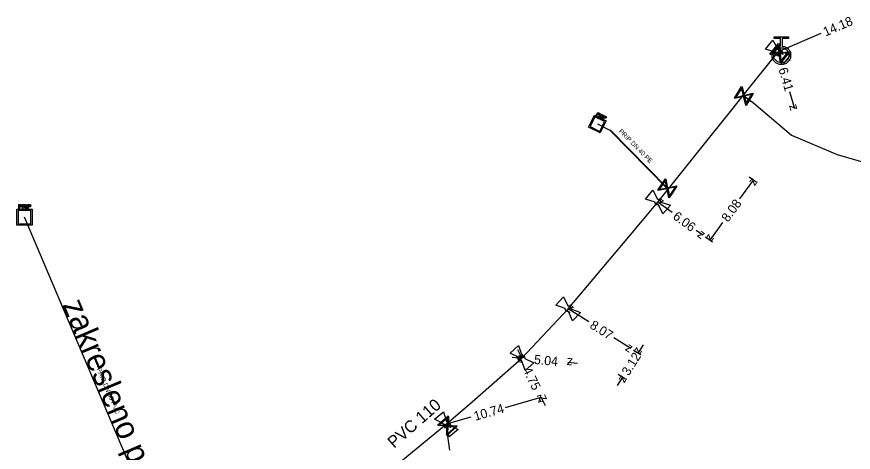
# Model space of a CAD drawing. Extents: x -638315 to -636370, y -1116147 to -1115110.
# Drawn here: x -637259.8 to -637168.7, y -1115907.4 to -1115860.1 of the extents above; entities that cross this region are included whole.
import ezdxf

# ---------------------------------------------------------------- set-up
doc = ezdxf.new("R2010")
doc.units = 0
for name, color, linetype in [('Default', 7, 'Continuous'), ('VP Chránička', 7, 'Continuous'), ('VP Chránička - okraje', 7, 'Continuous'), ('VP Hydrant', 7, 'Continuous'), ('VP Kótování', 7, 'Continuous'), ('VP Lomový bod', 7, 'Continuous'), ('VP Popis nerozlišený', 7, 'Continuous'), ('VP Popis přípojky', 7, 'Continuous'), ('VP Přípojka', 7, 'Continuous'), ('VP Řad', 7, 'Continuous'), ('VP Řad - popis', 7, 'Continuous'), ('VP Šachta', 7, 'Continuous'), ('VP Šoupě', 7, 'Continuous')]:
    doc.layers.add(name, color=color, linetype=linetype)

msp = doc.modelspace()

# ---------------------------------------------------------------- linework, layer by layer
at = {"layer": 'Default'}
for points in [[(-637176.478, -1115863.274), (-637176.119, -1115863.303), (-637175.861, -1115863.563), (-637175.57, -1115863.856), (-637175.57, -1115864.272), (-637175.57, -1115864.686), (-637175.863, -1115864.978), (-637176.156, -1115865.27), (-637176.572, -1115865.27), (-637176.984, -1115865.27), (-637177.277, -1115864.978), (-637177.57, -1115864.686), (-637177.57, -1115864.272), (-637177.57, -1115863.856), (-637177.279, -1115863.563), (-637177.021, -1115863.301), (-637176.662, -1115863.274)], [(-637176.572, -1115863.456), (-637176.91, -1115863.456), (-637177.147, -1115863.693), (-637177.384, -1115863.93), (-637177.384, -1115864.268), (-637177.384, -1115864.606), (-637177.147, -1115864.843), (-637176.91, -1115865.081), (-637176.572, -1115865.081), (-637176.236, -1115865.081), (-637175.998, -1115864.843), (-637175.759, -1115864.606), (-637175.759, -1115864.268), (-637175.759, -1115863.93), (-637175.997, -1115863.693), (-637176.234, -1115863.456), (-637176.572, -1115863.456)], [(-637176.92, -1115863.535), (-637176.826, -1115863.535), (-637176.736, -1115863.583), (-637176.646, -1115863.632), (-637176.596, -1115863.722), (-637176.545, -1115863.812), (-637176.545, -1115863.91), (-637176.545, -1115864.008), (-637176.594, -1115864.097), (-637176.644, -1115864.186), (-637176.733, -1115864.236), (-637176.823, -1115864.285), (-637176.92, -1115864.285), (-637177.017, -1115864.285), (-637177.107, -1115864.236), (-637177.196, -1115864.186), (-637177.246, -1115864.097), (-637177.295, -1115864.008), (-637177.295, -1115863.91), (-637177.295, -1115863.812), (-637177.245, -1115863.722), (-637177.194, -1115863.632), (-637177.105, -1115863.583), (-637177.015, -1115863.535), (-637176.92, -1115863.535)], [(-637176.92, -1115863.582), (-637177.003, -1115863.582), (-637177.082, -1115863.624), (-637177.16, -1115863.666), (-637177.204, -1115863.745), (-637177.248, -1115863.824), (-637177.248, -1115863.91), (-637177.248, -1115863.996), (-637177.205, -1115864.074), (-637177.162, -1115864.151), (-637177.084, -1115864.195), (-637177.005, -1115864.238), (-637176.92, -1115864.238), (-637176.835, -1115864.238), (-637176.756, -1115864.195), (-637176.678, -1115864.151), (-637176.635, -1115864.074), (-637176.592, -1115863.996), (-637176.592, -1115863.91), (-637176.592, -1115863.824), (-637176.636, -1115863.745), (-637176.681, -1115863.666), (-637176.759, -1115863.624), (-637176.838, -1115863.582), (-637176.92, -1115863.582)], [(-637176.863, -1115864.217), (-637176.915, -1115864.227), (-637176.969, -1115864.218), (-637177.052, -1115864.205), (-637177.115, -1115864.154), (-637177.179, -1115864.102), (-637177.211, -1115864.022), (-637177.232, -1115863.973), (-637177.233, -1115863.92)], [(-637176.977, -1115863.601), (-637176.926, -1115863.592), (-637176.873, -1115863.6), (-637176.788, -1115863.615), (-637176.724, -1115863.666), (-637176.661, -1115863.717), (-637176.629, -1115863.795), (-637176.609, -1115863.846), (-637176.608, -1115863.899)], [(-637196.454, -1115870.551), (-637196.422, -1115870.567), (-637196.406, -1115870.579), (-637196.386, -1115870.594), (-637196.374, -1115870.613), (-637196.363, -1115870.632), (-637196.363, -1115870.656), (-637196.364, -1115870.681), (-637196.375, -1115870.705), (-637196.396, -1115870.747), (-637196.435, -1115870.762), (-637196.474, -1115870.778), (-637196.543, -1115870.744)], [(-637196.524, -1115870.707), (-637196.483, -1115870.727), (-637196.458, -1115870.72), (-637196.434, -1115870.713), (-637196.42, -1115870.685), (-637196.41, -1115870.665), (-637196.413, -1115870.646), (-637196.416, -1115870.627), (-637196.431, -1115870.614), (-637196.44, -1115870.606), (-637196.47, -1115870.591)], [(-637196.224, -1115870.979), (-637196.228, -1115870.941), (-637196.233, -1115870.919), (-637196.237, -1115870.898), (-637196.244, -1115870.887), (-637196.251, -1115870.876), (-637196.26, -1115870.869), (-637196.265, -1115870.864), (-637196.282, -1115870.856)], [(-637196.223, -1115870.84), (-637196.193, -1115870.854), (-637196.174, -1115870.856), (-637196.154, -1115870.858), (-637196.14, -1115870.849), (-637196.125, -1115870.84), (-637196.117, -1115870.823), (-637196.106, -1115870.801), (-637196.116, -1115870.779), (-637196.125, -1115870.756), (-637196.161, -1115870.738)], [(-637196.145, -1115870.701), (-637196.102, -1115870.722), (-637196.083, -1115870.742), (-637196.065, -1115870.762), (-637196.063, -1115870.79), (-637196.06, -1115870.818), (-637196.073, -1115870.845), (-637196.09, -1115870.88), (-637196.123, -1115870.892), (-637196.156, -1115870.905), (-637196.206, -1115870.889), (-637196.193, -1115870.906), (-637196.188, -1115870.918), (-637196.178, -1115870.943), (-637196.174, -1115870.978)], [(-637195.733, -1115870.902), (-637195.701, -1115870.918), (-637195.685, -1115870.93), (-637195.664, -1115870.945), (-637195.653, -1115870.964), (-637195.642, -1115870.983), (-637195.642, -1115871.007), (-637195.643, -1115871.032), (-637195.654, -1115871.056), (-637195.675, -1115871.098), (-637195.714, -1115871.113), (-637195.753, -1115871.129), (-637195.822, -1115871.096)], [(-637195.803, -1115871.058), (-637195.762, -1115871.079), (-637195.737, -1115871.071), (-637195.713, -1115871.064), (-637195.699, -1115871.036), (-637195.689, -1115871.016), (-637195.692, -1115870.997), (-637195.695, -1115870.978), (-637195.71, -1115870.965), (-637195.719, -1115870.957), (-637195.749, -1115870.942)], [(-637189.97, -1115880.548), (-637190.022, -1115880.557), (-637190.076, -1115880.547), (-637190.159, -1115880.531), (-637190.221, -1115880.479), (-637190.284, -1115880.426), (-637190.314, -1115880.344), (-637190.333, -1115880.295), (-637190.333, -1115880.242)], [(-637190.07, -1115879.929), (-637190.018, -1115879.922), (-637189.966, -1115879.931), (-637189.881, -1115879.948), (-637189.819, -1115880.001), (-637189.756, -1115880.053), (-637189.727, -1115880.132), (-637189.708, -1115880.184), (-637189.707, -1115880.236)], [(-637259.447, -1115880.507), (-637259.404, -1115880.507), (-637259.381, -1115880.511), (-637259.35, -1115880.517), (-637259.328, -1115880.532), (-637259.306, -1115880.547), (-637259.293, -1115880.573), (-637259.281, -1115880.599), (-637259.281, -1115880.631), (-637259.281, -1115880.687), (-637259.315, -1115880.725), (-637259.35, -1115880.762), (-637259.441, -1115880.762)], [(-637259.441, -1115880.712), (-637259.385, -1115880.712), (-637259.362, -1115880.692), (-637259.34, -1115880.671), (-637259.34, -1115880.633), (-637259.34, -1115880.607), (-637259.353, -1115880.588), (-637259.366, -1115880.569), (-637259.388, -1115880.563), (-637259.403, -1115880.558), (-637259.442, -1115880.558)], [(-637258.973, -1115880.848), (-637258.998, -1115880.809), (-637259.014, -1115880.788), (-637259.031, -1115880.768), (-637259.044, -1115880.76), (-637259.057, -1115880.752), (-637259.07, -1115880.749), (-637259.079, -1115880.746), (-637259.101, -1115880.746)], [(-637259.045, -1115880.697), (-637259.006, -1115880.697), (-637258.984, -1115880.689), (-637258.962, -1115880.681), (-637258.951, -1115880.664), (-637258.94, -1115880.646), (-637258.94, -1115880.624), (-637258.94, -1115880.595), (-637258.962, -1115880.575), (-637258.984, -1115880.555), (-637259.032, -1115880.555)], [(-637259.033, -1115880.507), (-637258.976, -1115880.507), (-637258.946, -1115880.519), (-637258.916, -1115880.53), (-637258.899, -1115880.56), (-637258.881, -1115880.589), (-637258.881, -1115880.624), (-637258.881, -1115880.671), (-637258.91, -1115880.702), (-637258.94, -1115880.733), (-637259.001, -1115880.741), (-637258.979, -1115880.753), (-637258.968, -1115880.763), (-637258.943, -1115880.785), (-637258.921, -1115880.82)], [(-637258.484, -1115880.508), (-637258.442, -1115880.508), (-637258.418, -1115880.513), (-637258.387, -1115880.519), (-637258.366, -1115880.533), (-637258.344, -1115880.548), (-637258.331, -1115880.574), (-637258.319, -1115880.601), (-637258.319, -1115880.633), (-637258.319, -1115880.689), (-637258.353, -1115880.726), (-637258.387, -1115880.763), (-637258.478, -1115880.763)], [(-637258.478, -1115880.714), (-637258.423, -1115880.714), (-637258.4, -1115880.693), (-637258.377, -1115880.673), (-637258.377, -1115880.634), (-637258.377, -1115880.608), (-637258.39, -1115880.589), (-637258.404, -1115880.57), (-637258.426, -1115880.564), (-637258.44, -1115880.56), (-637258.48, -1115880.56)], [(-637199.767, -1115892.151), (-637199.819, -1115892.157), (-637199.873, -1115892.144), (-637199.954, -1115892.124), (-637200.014, -1115892.068), (-637200.074, -1115892.012), (-637200.1, -1115891.929), (-637200.116, -1115891.879), (-637200.113, -1115891.826)], [(-637199.833, -1115891.528), (-637199.782, -1115891.523), (-637199.73, -1115891.535), (-637199.646, -1115891.556), (-637199.586, -1115891.612), (-637199.527, -1115891.668), (-637199.502, -1115891.749), (-637199.485, -1115891.801), (-637199.488, -1115891.854)], [(-637204.827, -1115897.513), (-637204.88, -1115897.513), (-637204.932, -1115897.495), (-637205.011, -1115897.468), (-637205.065, -1115897.406), (-637205.119, -1115897.344), (-637205.137, -1115897.259), (-637205.148, -1115897.208), (-637205.14, -1115897.155)], [(-637204.833, -1115896.886), (-637204.781, -1115896.886), (-637204.73, -1115896.903), (-637204.649, -1115896.933), (-637204.595, -1115896.994), (-637204.541, -1115897.056), (-637204.524, -1115897.138), (-637204.513, -1115897.192), (-637204.521, -1115897.244)], [(-637213.069, -1115904.721), (-637213.122, -1115904.72), (-637213.173, -1115904.701), (-637213.252, -1115904.67), (-637213.303, -1115904.607), (-637213.355, -1115904.544), (-637213.37, -1115904.458), (-637213.38, -1115904.406), (-637213.37, -1115904.354)], [(-637213.053, -1115904.095), (-637213.002, -1115904.097), (-637212.951, -1115904.116), (-637212.871, -1115904.148), (-637212.82, -1115904.211), (-637212.768, -1115904.275), (-637212.754, -1115904.358), (-637212.744, -1115904.411), (-637212.754, -1115904.463)]]:
    msp.add_open_spline(points, degree=3, dxfattribs=at)
at = {"layer": 'VP Chránička'}
msp.add_lwpolyline([(-637188.995, -1115878.735), (-637195.242, -1115872.412)], dxfattribs=at)
at = {"layer": 'VP Chránička - okraje'}
for points in [[(-637189.017, -1115878.757), (-637195.264, -1115872.434)], [(-637195.219, -1115872.39), (-637188.973, -1115878.713)]]:
    msp.add_lwpolyline(points, dxfattribs=at)
at = {"layer": 'VP Hydrant'}
msp.add_lwpolyline([(-637176.662, -1115863.274), (-637176.662, -1115862.454), (-637177.351, -1115862.454), (-637177.351, -1115862.27), (-637175.789, -1115862.27), (-637175.789, -1115862.454), (-637176.478, -1115862.454), (-637176.478, -1115863.274)], dxfattribs=at)
at = {"layer": 'VP Kótování'}
for points in [[(-637172.285, -1115861.921), (-637176.92, -1115863.91)], [(-637176.519, -1115865.291), (-637176.92, -1115863.91)], [(-637175.672, -1115868.204), (-637175.13, -1115870.07)], [(-637180.077, -1115877.496), (-637179.324, -1115878.047)], [(-637181.1, -1115879.886), (-637179.606, -1115877.84)], [(-637188.465, -1115881.375), (-637190.02, -1115880.24)], [(-637182.992, -1115882.477), (-637184.37, -1115884.365)], [(-637185.848, -1115883.287), (-637185.124, -1115883.815)], [(-637184.841, -1115884.021), (-637184.088, -1115884.572)], [(-637197.548, -1115893.26), (-637199.8, -1115891.84)], [(-637194.835, -1115894.971), (-637192.977, -1115896.143)], [(-637191.618, -1115895.758), (-637192.179, -1115896.647)], [(-637205.292, -1115896.257), (-637204.83, -1115897.2)], [(-637192.681, -1115896.33), (-637191.882, -1115896.833)], [(-637205.875, -1115897.098), (-637204.83, -1115897.2)], [(-637198.765, -1115897.792), (-637199.81, -1115897.69)], [(-637194.402, -1115900.172), (-637193.842, -1115899.284)], [(-637194.344, -1115898.967), (-637193.545, -1115899.47)], [(-637206.621, -1115902.569), (-637202.74, -1115901.46)], [(-637202.278, -1115902.403), (-637202.74, -1115901.46)], [(-637210.379, -1115903.643), (-637213.062, -1115904.409)], [(-637212.681, -1115907.23), (-637213.062, -1115904.409)]]:
    msp.add_lwpolyline(points, dxfattribs=at)
at = {"layer": 'VP Lomový bod'}
for points in [[(-637178.286, -1115863.615), (-637177.504, -1115862.64), (-637176.977, -1115863.601)], [(-637177.233, -1115863.92), (-637178.286, -1115863.615)], [(-637176.608, -1115863.899), (-637175.554, -1115864.204), (-637176.336, -1115865.179), (-637176.863, -1115864.217)], [(-637191.378, -1115879.912), (-637190.573, -1115878.956), (-637190.07, -1115879.929)], [(-637190.333, -1115880.242), (-637191.378, -1115879.912)], [(-637189.707, -1115880.236), (-637188.661, -1115880.567), (-637189.467, -1115881.523), (-637189.97, -1115880.548)], [(-637201.139, -1115891.44), (-637200.284, -1115890.529), (-637199.833, -1115891.528)], [(-637200.113, -1115891.826), (-637201.139, -1115891.44)], [(-637199.488, -1115891.854), (-637198.461, -1115892.24), (-637199.316, -1115893.151), (-637199.767, -1115892.151)], [(-637206.124, -1115896.671), (-637205.183, -1115895.848), (-637204.833, -1115896.886)], [(-637205.14, -1115897.155), (-637206.124, -1115896.671)], [(-637204.521, -1115897.244), (-637203.536, -1115897.729), (-637204.477, -1115898.552), (-637204.827, -1115897.513)], [(-637214.337, -1115903.837), (-637213.369, -1115903.046), (-637213.053, -1115904.095)], [(-637213.37, -1115904.354), (-637214.337, -1115903.837)], [(-637212.754, -1115904.463), (-637211.786, -1115904.981), (-637212.754, -1115905.772), (-637213.069, -1115904.721)]]:
    msp.add_lwpolyline(points, dxfattribs=at)
at = {"layer": 'VP Přípojka'}
for points in [[(-637176.637, -1115864.19), (-637176.766, -1115864.037), (-637176.92, -1115863.91)], [(-637180.72, -1115868.647), (-637180.66, -1115868.69), (-637179.56, -1115869.48), (-637175.49, -1115872.98), (-637170.49, -1115875.08), (-637164.61, -1115876.76), (-637159.9, -1115877.14), (-637154.27, -1115876.95)], [(-637196.612, -1115871.747), (-637195.242, -1115872.412), (-637188.995, -1115878.735), (-637188.874, -1115878.812)], [(-637244.12, -1115916.89), (-637258.991, -1115881.881)], [(-637213.062, -1115904.409), (-637212.92, -1115904.55)]]:
    msp.add_lwpolyline(points, dxfattribs=at)
at = {"layer": 'VP Řad'}
msp.add_lwpolyline([(-637237.94, -1115924.63), (-637234.89, -1115921.16), (-637222.26, -1115911.93), (-637213.062, -1115904.409), (-637210.258, -1115901.954), (-637204.83, -1115897.2), (-637199.8, -1115891.84), (-637193.2, -1115884.012), (-637190.02, -1115880.24), (-637188.874, -1115878.812), (-637184.355, -1115873.178), (-637181.977, -1115870.214), (-637180.72, -1115868.647), (-637176.92, -1115863.91)], dxfattribs=at)
at = {"layer": 'VP Šachta'}
for points in [[(-637195.661, -1115871.405), (-637196.295, -1115872.711), (-637197.566, -1115872.094), (-637196.933, -1115870.788), (-637195.661, -1115871.405)], [(-637196.878, -1115870.952), (-637197.404, -1115872.036), (-637196.35, -1115872.548), (-637195.824, -1115871.464), (-637196.878, -1115870.952)], [(-637196.732, -1115870.816), (-637196.575, -1115870.493), (-637196.454, -1115870.551)], [(-637196.543, -1115870.744), (-637196.626, -1115870.704), (-637196.69, -1115870.836), (-637196.732, -1115870.816)], [(-637196.47, -1115870.591), (-637196.552, -1115870.551), (-637196.608, -1115870.667)], [(-637196.608, -1115870.667), (-637196.524, -1115870.707)], [(-637196.444, -1115870.955), (-637196.287, -1115870.632), (-637196.145, -1115870.701)], [(-637196.282, -1115870.856), (-637196.331, -1115870.832), (-637196.401, -1115870.976), (-637196.444, -1115870.955)], [(-637196.161, -1115870.738), (-637196.262, -1115870.689), (-637196.314, -1115870.796)], [(-637196.314, -1115870.796), (-637196.223, -1115870.84)], [(-637196.174, -1115870.978), (-637196.161, -1115871.093), (-637196.214, -1115871.066), (-637196.224, -1115870.979)], [(-637196.117, -1115871.115), (-637195.961, -1115870.792), (-637195.919, -1115870.812), (-637196.075, -1115871.135), (-637196.117, -1115871.115)], [(-637196.011, -1115871.167), (-637195.854, -1115870.844), (-637195.733, -1115870.902)], [(-637195.822, -1115871.096), (-637195.905, -1115871.055), (-637195.969, -1115871.187), (-637196.011, -1115871.167)], [(-637195.749, -1115870.942), (-637195.831, -1115870.902), (-637195.887, -1115871.018)], [(-637195.887, -1115871.018), (-637195.803, -1115871.058)], [(-637258.143, -1115881.014), (-637258.143, -1115882.756), (-637259.839, -1115882.756), (-637259.839, -1115881.014), (-637258.143, -1115881.014)], [(-637259.694, -1115881.162), (-637259.694, -1115882.608), (-637258.288, -1115882.608), (-637258.288, -1115881.162), (-637259.694, -1115881.162)], [(-637259.608, -1115880.938), (-637259.608, -1115880.507), (-637259.447, -1115880.507)], [(-637259.441, -1115880.762), (-637259.552, -1115880.762), (-637259.552, -1115880.938), (-637259.608, -1115880.938)], [(-637259.442, -1115880.558), (-637259.552, -1115880.558), (-637259.552, -1115880.712)], [(-637259.552, -1115880.712), (-637259.441, -1115880.712)], [(-637259.224, -1115880.938), (-637259.224, -1115880.507), (-637259.033, -1115880.507)], [(-637259.101, -1115880.746), (-637259.167, -1115880.746), (-637259.167, -1115880.938), (-637259.224, -1115880.938)], [(-637259.032, -1115880.555), (-637259.167, -1115880.555), (-637259.167, -1115880.697)], [(-637259.167, -1115880.697), (-637259.045, -1115880.697)], [(-637258.921, -1115880.82), (-637258.846, -1115880.938), (-637258.918, -1115880.938), (-637258.973, -1115880.848)], [(-637258.787, -1115880.939), (-637258.787, -1115880.508), (-637258.732, -1115880.508), (-637258.732, -1115880.939), (-637258.787, -1115880.939)], [(-637258.645, -1115880.939), (-637258.645, -1115880.508), (-637258.484, -1115880.508)], [(-637258.478, -1115880.763), (-637258.59, -1115880.763), (-637258.59, -1115880.939), (-637258.645, -1115880.939)], [(-637258.48, -1115880.56), (-637258.59, -1115880.56), (-637258.59, -1115880.714)], [(-637258.59, -1115880.714), (-637258.478, -1115880.714)]]:
    msp.add_lwpolyline(points, dxfattribs=at)
at = {"layer": 'VP Šoupě'}
for points in [[(-637175.709, -1115863.925), (-637176.648, -1115865.095), (-637176.699, -1115865.053), (-637176.709, -1115864.925), (-637176.802, -1115864.09), (-637177.767, -1115864.197), (-637177.818, -1115864.156), (-637176.879, -1115862.986), (-637176.828, -1115863.027), (-637176.724, -1115863.993), (-637175.889, -1115863.901), (-637175.761, -1115863.883), (-637175.709, -1115863.925)], [(-637177.65, -1115864.096), (-637176.812, -1115864.003), (-637176.904, -1115863.167), (-637177.65, -1115864.096)], [(-637175.881, -1115863.989), (-637176.714, -1115864.081), (-637176.622, -1115864.913), (-637175.881, -1115863.989)], [(-637179.631, -1115868.434), (-637180.404, -1115869.719), (-637180.46, -1115869.685), (-637180.487, -1115869.56), (-637180.691, -1115868.745), (-637181.633, -1115868.98), (-637181.689, -1115868.946), (-637180.916, -1115867.661), (-637180.86, -1115867.695), (-637180.627, -1115868.638), (-637179.812, -1115868.434), (-637179.687, -1115868.4), (-637179.631, -1115868.434)], [(-637181.53, -1115868.864), (-637180.712, -1115868.659), (-637180.916, -1115867.843), (-637181.53, -1115868.864)], [(-637179.792, -1115868.521), (-637180.606, -1115868.723), (-637180.403, -1115869.535), (-637179.792, -1115868.521)], [(-637187.956, -1115878.521), (-637188.78, -1115879.774), (-637188.836, -1115879.738), (-637188.857, -1115879.611), (-637189.028, -1115878.789), (-637189.979, -1115878.986), (-637190.034, -1115878.95), (-637189.21, -1115877.696), (-637189.154, -1115877.733), (-637188.96, -1115878.684), (-637188.138, -1115878.514), (-637188.011, -1115878.484), (-637187.956, -1115878.521)], [(-637189.872, -1115878.874), (-637189.046, -1115878.702), (-637189.217, -1115877.879), (-637189.872, -1115878.874)], [(-637188.121, -1115878.601), (-637188.942, -1115878.771), (-637188.772, -1115879.59), (-637188.121, -1115878.601)], [(-637211.861, -1115904.62), (-637212.99, -1115905.608), (-637213.033, -1115905.559), (-637213.021, -1115905.431), (-637212.966, -1115904.593), (-637213.935, -1115904.53), (-637213.978, -1115904.48), (-637212.85, -1115903.492), (-637212.806, -1115903.541), (-637212.872, -1115904.511), (-637212.034, -1115904.565), (-637211.905, -1115904.571), (-637211.861, -1115904.62)], [(-637213.802, -1115904.45), (-637212.96, -1115904.505), (-637212.906, -1115903.666), (-637213.802, -1115904.45)], [(-637212.042, -1115904.653), (-637212.878, -1115904.599), (-637212.933, -1115905.434), (-637212.042, -1115904.653)]]:
    msp.add_lwpolyline(points, dxfattribs=at)

# ---------------------------------------------------------------- texts
at = {"layer": 'VP Kótování'}
for s, rotation, p in [('14.18', 23.2198, (-637171.766, -1115862.243)), ('z', 203.21984, (-637176.658, -1115863.253)), ('z', 106.20306, (-637176.3, -1115864.251)), ('6.41', 286.20302, (-637176.901, -1115865.767)), ('z', 286.20304, (-637175.75, -1115869.729)), ('z', 53.86628, (-637179.497, -1115878.539)), ('z', 143.86351, (-637189.321, -1115880.131)), ('8.08', 53.86628, (-637182.382, -1115882.489)), ('6.06', 323.86353, (-637188.478, -1115881.985)), ('z', 323.86355, (-637185.823, -1115883.924)), ('z', 233.86626, (-637184.479, -1115883.667)), ('z', 147.76198, (-637199.11, -1115891.684)), ('8.07', 327.762, (-637197.519, -1115893.87)), ('z', 327.76196, (-637193.667, -1115896.299)), ('z', 296.13302, (-637205.499, -1115896.971)), ('3.12', 57.7628, (-637193.197, -1115899.198)), ('z', 237.76278, (-637192.335, -1115895.957)), ('z', 354.42506, (-637205.376, -1115897.649)), ('5.04', 354.42505, (-637203.545, -1115897.828)), ('z', 174.42503, (-637199.264, -1115897.241)), ('4.75', 296.13306, (-637204.763, -1115898.471)), ('z', 57.7628, (-637193.685, -1115899.973)), ('z', 15.94467, (-637203.083, -1115902.078)), ('z', 116.13304, (-637202.071, -1115901.689)), ('10.74', 15.94467, (-637209.905, -1115904.027)), ('z', 195.94465, (-637212.719, -1115903.791)), ('z', 97.6944, (-637212.5, -1115904.838))]:
    msp.add_text(s, height=1, rotation=rotation, dxfattribs=at).set_placement(p)
at = {"layer": 'VP Popis nerozlišený'}
msp.add_text('zakresleno približne', height=2.5, rotation=293.01463, dxfattribs=at).set_placement((-637254.895, -1115891.398))
at = {"layer": 'VP Popis přípojky'}
for s, rotation, p in [('PRIP DN 40 PE', 314.6525, (-637194.317, -1115872.588)), ('PRIP DN 90 PVC', 293.01463, (-637251.152, -1115898.385))]:
    msp.add_text(s, height=0.5, rotation=rotation, dxfattribs=at).set_placement(p)
at = {"layer": 'VP Řad - popis'}
msp.add_text('PVC 110', height=1.3, rotation=41.20959, dxfattribs=at).set_placement((-637218.754, -1115907.075))

doc.saveas('drawing.dxf')
